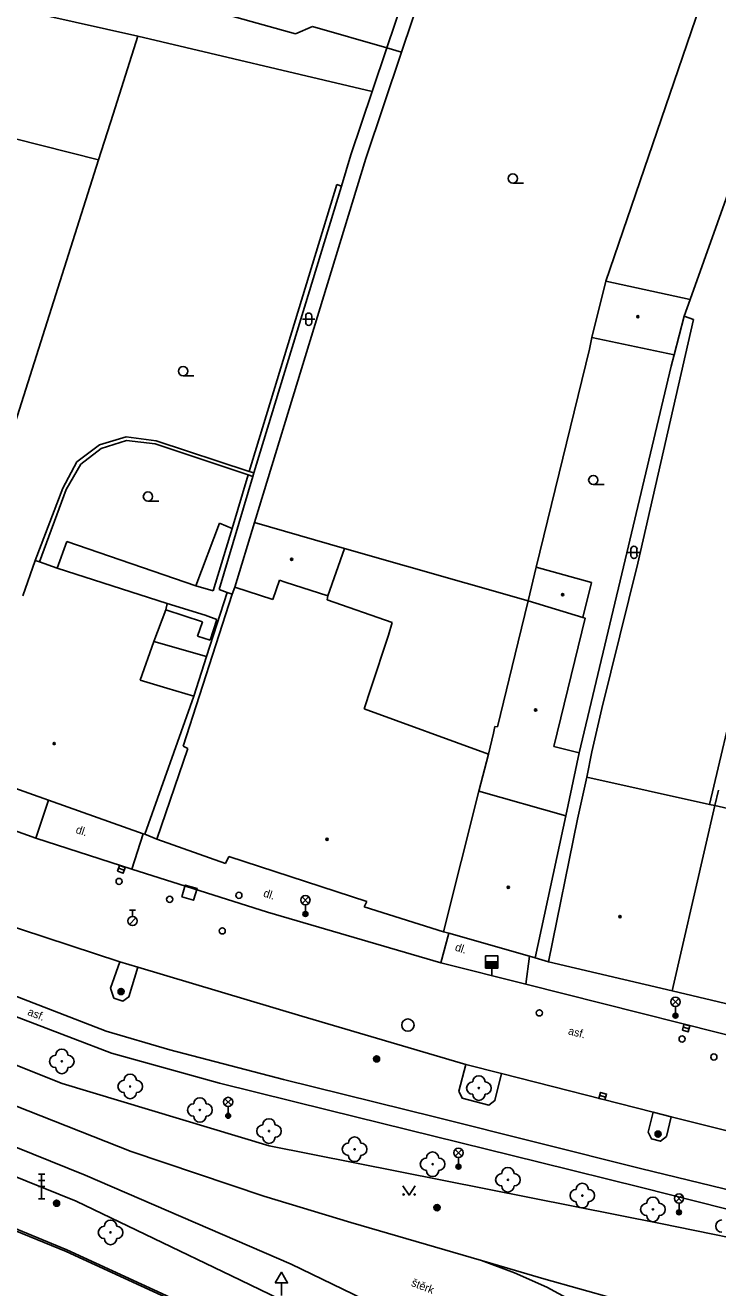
# Model space of a CAD drawing. Extents: x -600309 to -598967, y -1161267 to -1160292.
# Drawn here: x -600017 to -599960.7, y -1161167.5 to -1161065 of the extents above; entities that cross this region are included whole.
import ezdxf

# ---------------------------------------------------------------- set-up
doc = ezdxf.new("R2010")
doc.units = 0
for name, color, linetype in [('Level 10', 7, 'Continuous'), ('Level 11', 7, 'Continuous'), ('Level 13', 7, 'Continuous'), ('Level 14', 7, 'Continuous'), ('Level 22', 7, 'Continuous'), ('Level 25', 7, 'Continuous'), ('Level 26', 7, 'Continuous'), ('Level 27', 7, 'Continuous'), ('Level 28', 7, 'Continuous'), ('Level 33', 7, 'Continuous'), ('Level 34', 7, 'Continuous'), ('Level 36', 7, 'Continuous'), ('Level 39', 7, 'Continuous'), ('Level 40', 7, 'Continuous'), ('Level 5', 7, 'Continuous'), ('Level 51', 7, 'Continuous'), ('Level 52', 7, 'Continuous'), ('Level 54', 7, 'Continuous'), ('Level 7', 7, 'Continuous'), ('Level 9', 7, 'Continuous')]:
    doc.layers.add(name, color=color, linetype=linetype)

msp = doc.modelspace()

# ---------------------------------------------------------------- linework, layer by layer
at = {"layer": 'Level 10'}
for points in [[(-600016.1599, -1161131.01), (-600028.7199, -1161126.53)], [(-600008.36, -1161133.53), (-600016.1599, -1161131.01)], [(-599983.26, -1161141.1599), (-599997.33, -1161137.03), (-600008.36, -1161133.53)], [(-600028.39, -1161134.63), (-600023.46, -1161136.43), (-600009.34, -1161141.08)], [(-600009.34, -1161141.08), (-600007.88, -1161141.51)], [(-600007.88, -1161141.51), (-599994.56, -1161145.4699), (-599981.23, -1161149.4)], [(-599976.34, -1161142.88), (-599983.26, -1161141.1599)], [(-599932.42, -1161153.96), (-599936.27, -1161153.08), (-599952.82, -1161148.99), (-599954.4099, -1161148.4099), (-599976.34, -1161142.88)], [(-599981.23, -1161149.4), (-599978.33, -1161150.13)], [(-599978.33, -1161150.13), (-599966, -1161153.27)], [(-599966, -1161153.27), (-599964.52, -1161153.65)], [(-599964.52, -1161153.65), (-599939.5, -1161159.9099)]]:
    msp.add_lwpolyline(points, dxfattribs=at)
at = {"layer": 'Level 11'}
for points in [[(-599992.38, -1161153.1), (-600001.23, -1161150.93), (-600010.01, -1161148.49), (-600025.63, -1161142.54), (-600047.8, -1161133.93), (-600066.9099, -1161126.25), (-600071.24, -1161124.36), (-600084.2199, -1161118.67), (-600093.96, -1161114.55), (-600106.27, -1161109.6599), (-600141.52, -1161095.62), (-600170.63, -1161084.1), (-600197.34, -1161074.45), (-600220.27, -1161066.13)], [(-600029.52, -1161071.27), (-600011.07, -1161075.93)], [(-600016.1599, -1161131.01), (-600015.13, -1161127.94)], [(-600008.36, -1161133.53), (-600007.46, -1161130.6599)], [(-600006.35, -1161131.1), (-600007.32, -1161130.71)], [(-600010.46, -1161146.71), (-600038.83, -1161135.74)], [(-599983.26, -1161141.1599), (-599982.59, -1161138.75)], [(-599976.34, -1161142.88), (-599976.05, -1161140.61)], [(-599974.49, -1161141.08), (-599975.57, -1161140.75)], [(-600007.88, -1161141.51), (-600008.62, -1161143.92), (-600009.11, -1161144.26), (-600009.83, -1161144.01), (-600010.1, -1161143.2), (-600009.34, -1161141.08)], [(-600010.46, -1161146.71), (-600005.28, -1161148.21), (-599996.03, -1161150.62), (-599983.6599, -1161153.67)], [(-599978.33, -1161150.13), (-599978.86, -1161152.33), (-599979.35, -1161152.7), (-599981.53, -1161152.15), (-599981.79, -1161151.58), (-599981.23, -1161149.4)], [(-599992.38, -1161153.1), (-599975.26, -1161157.34), (-599966.94, -1161159.4), (-599946.69, -1161164.52), (-599944.2199, -1161165.09)], [(-599964.52, -1161153.65), (-599964.92, -1161155.25), (-599965.4, -1161155.64), (-599966.13, -1161155.44), (-599966.39, -1161154.89), (-599966, -1161153.27)], [(-599967.01, -1161157.86), (-599983.6599, -1161153.67)], [(-599863.64, -1161184.68), (-599889.92, -1161177.65), (-599907.2809, -1161172.7877), (-599916.52, -1161170.2), (-599932.76, -1161165.82), (-599934.95, -1161165.24), (-599946.09, -1161162.38), (-599957.33, -1161160.21), (-599967.01, -1161157.86)]]:
    msp.add_lwpolyline(points, dxfattribs=at)
at = {"layer": 'Level 13'}
for points in [[(-600008.43, -1161156.46), (-600028.28, -1161148.6599)], [(-600029.42, -1161151.45), (-600020.65, -1161154.98), (-600012.1599, -1161158.38)], [(-600008.43, -1161156.46), (-599997.65, -1161160.09), (-599990.56, -1161162.23), (-599979.95, -1161165.32)], [(-600012.1599, -1161158.38), (-599995.42, -1161165.61)], [(-599979.95, -1161165.32), (-599977.26, -1161166.33), (-599974.63, -1161167.5), (-599972.08, -1161168.86), (-599969.64, -1161170.37)], [(-599979.95, -1161165.32), (-599974.87, -1161166.8), (-599969.08, -1161168.43), (-599962.98, -1161170.1599), (-599954.07, -1161172.69)], [(-599995.42, -1161165.61), (-599987.87, -1161169.28), (-599986.57, -1161169.9099)]]:
    msp.add_lwpolyline(points, dxfattribs=at)
at = {"layer": 'Level 14'}
msp.add_lwpolyline([(-600209.68, -1161081.29), (-600207.11, -1161082.21), (-600207.29, -1161083.09), (-600203.81, -1161084.18), (-600189.29, -1161089.35), (-600180.35, -1161092.69), (-600160.29, -1161100.77), (-600144.28, -1161107.3), (-600111.05, -1161120.77), (-600060.34, -1161141.37), (-600012.89, -1161160.49), (-600000.2641, -1161166.5758), (-599990.94, -1161171.07)], dxfattribs=at)
at = {"layer": 'Level 22'}
for centre in [(-600014.06, -1161149.15), (-600008.5, -1161151.19), (-599980.1599, -1161151.32), (-600002.84, -1161153.1), (-599997.2199, -1161154.81), (-599990.26, -1161156.29), (-599983.92, -1161157.5), (-599977.8, -1161158.77), (-599971.75, -1161160.05), (-599966.01, -1161161.17), (-600010.1, -1161163.04)]:
    msp.add_circle(centre, 0.05, dxfattribs=at)
for centre, start, end in [((-600014.56, -1161149.15), 90, 270), ((-600014.06, -1161148.65), 0, 180), ((-600013.56, -1161149.15), 270, 90), ((-600014.06, -1161149.65), 180, 0), ((-600008.5, -1161150.69), 0, 180), ((-600009, -1161151.19), 90, 270), ((-600008, -1161151.19), 270, 90), ((-599980.6599, -1161151.32), 90, 270), ((-599980.1599, -1161150.82), 0, 180), ((-599979.6599, -1161151.32), 270, 90), ((-600008.5, -1161151.69), 180, 0), ((-600002.84, -1161152.6), 0, 180), ((-599980.1599, -1161151.82), 180, 0), ((-600003.34, -1161153.1), 90, 270), ((-600002.34, -1161153.1), 270, 90), ((-600002.84, -1161153.6), 180, 0), ((-599997.2199, -1161154.31), 0, 180), ((-599997.7199, -1161154.81), 90, 270), ((-599997.2199, -1161155.31), 180, 0), ((-599996.7199, -1161154.81), 270, 90), ((-599990.26, -1161155.79), 0, 180), ((-599990.76, -1161156.29), 90, 270), ((-599989.76, -1161156.29), 270, 90), ((-599990.26, -1161156.79), 180, 0), ((-599984.42, -1161157.5), 90, 270), ((-599983.92, -1161157), 0, 180), ((-599983.42, -1161157.5), 270, 90), ((-599983.92, -1161158), 180, 0), ((-599978.3, -1161158.77), 90, 270), ((-599977.8, -1161158.27), 0, 180), ((-599977.3, -1161158.77), 270, 90), ((-599977.8, -1161159.27), 180, 0), ((-599971.75, -1161159.55), 0, 180), ((-599972.25, -1161160.05), 90, 270), ((-599971.25, -1161160.05), 270, 90), ((-599966.01, -1161160.67), 0, 180), ((-599971.75, -1161160.55), 180, 0), ((-599966.51, -1161161.17), 90, 270), ((-599965.51, -1161161.17), 270, 90), ((-600010.1, -1161162.54), 0, 180), ((-599966.01, -1161161.67), 180, 0), ((-599960.4099, -1161162.53), 90, 270), ((-600010.6, -1161163.04), 90, 270), ((-600009.6, -1161163.04), 270, 90), ((-600010.1, -1161163.54), 180, 0)]:
    msp.add_arc(centre, 0.5, start, end, dxfattribs=at)
at = {"layer": 'Level 25'}
for centre, radius in [((-600009.24, -1161143.48), 0.25), ((-600009.24, -1161143.48), 0.2), ((-600009.24, -1161143.48), 0.15), ((-600009.24, -1161143.48), 0.1), ((-600009.24, -1161143.48), 0.05), ((-599988.48, -1161148.95), 0.25), ((-599988.48, -1161148.95), 0.2), ((-599988.48, -1161148.95), 0.15), ((-599988.48, -1161148.95), 0.1), ((-599988.48, -1161148.95), 0.05), ((-599965.59, -1161155.06), 0.25), ((-599965.59, -1161155.06), 0.2), ((-599965.59, -1161155.06), 0.15), ((-599965.59, -1161155.06), 0.1), ((-599965.59, -1161155.06), 0.05), ((-600014.49, -1161160.67), 0.25), ((-600014.49, -1161160.67), 0.2), ((-600014.49, -1161160.67), 0.15), ((-600014.49, -1161160.67), 0.1), ((-600014.49, -1161160.67), 0.05), ((-599983.56, -1161161.03), 0.25), ((-599983.56, -1161161.03), 0.2), ((-599983.56, -1161161.03), 0.15), ((-599983.56, -1161161.03), 0.1), ((-599983.56, -1161161.03), 0.05)]:
    msp.add_circle(centre, radius, dxfattribs=at)
at = {"layer": 'Level 26'}
msp.add_lwpolyline([(-600004.3095, -1161135.791), (-600003.349, -1161136.0695), (-600003.0705, -1161135.109), (-600004.031, -1161134.8305)], close=True, dxfattribs=at)
at = {"layer": 'Level 27'}
for p, q in [((-600009.4664, -1161133.4686), (-600008.9936, -1161133.6314)), ((-599963.5514, -1161146.3851), (-599963.0686, -1161146.5149)), ((-599970.3314, -1161151.9151), (-599969.8486, -1161152.0449))]:
    msp.add_line(p, q, dxfattribs=at)
for points in [[(-600009.5477, -1161133.705), (-600009.075, -1161133.8677), (-600008.9123, -1161133.395), (-600009.385, -1161133.2323)], [(-599963.6163, -1161146.6266), (-599963.1334, -1161146.7563), (-599963.0037, -1161146.2734), (-599963.4866, -1161146.1437)], [(-599970.3963, -1161152.1566), (-599969.9134, -1161152.2863), (-599969.7837, -1161151.8034), (-599970.2666, -1161151.6737)]]:
    msp.add_lwpolyline(points, close=True, dxfattribs=at)
msp.add_circle((-599985.93, -1161146.2), 0.5, dxfattribs=at)
at = {"layer": 'Level 28'}
for p, q in [((-600008.568, -1161138.022), (-600008.038, -1161137.492)), ((-600008.56, -1161136.875), (-600008.06, -1161136.875)), ((-600008.31, -1161137.375), (-600008.31, -1161136.875)), ((-599979.61, -1161141.08), (-599978.61, -1161141.08)), ((-599979.61, -1161141.13), (-599978.61, -1161141.13)), ((-599979.61, -1161141.18), (-599978.61, -1161141.18)), ((-599979.61, -1161141.23), (-599978.61, -1161141.23)), ((-599979.61, -1161141.28), (-599978.61, -1161141.28)), ((-599979.61, -1161141.33), (-599978.61, -1161141.33)), ((-599979.61, -1161141.38), (-599978.61, -1161141.38)), ((-599979.61, -1161141.43), (-599978.61, -1161141.43)), ((-599979.61, -1161141.48), (-599978.61, -1161141.48)), ((-599979.61, -1161141.53), (-599978.61, -1161141.53)), ((-599979.11, -1161141.58), (-599979.11, -1161142.11))]:
    msp.add_line(p, q, dxfattribs=at)
msp.add_lwpolyline([(-599979.61, -1161141.58), (-599978.61, -1161141.58), (-599978.61, -1161140.58), (-599979.61, -1161140.58)], close=True, dxfattribs=at)
for centre, radius in [((-600009.4, -1161134.54), 0.25), ((-600005.29, -1161135.99), 0.25), ((-599999.67, -1161135.67), 0.25), ((-600008.31, -1161137.75), 0.375), ((-600001.02, -1161138.55), 0.25), ((-599975.24, -1161145.21), 0.25), ((-599963.64, -1161147.33), 0.25), ((-599961.06, -1161148.8), 0.25)]:
    msp.add_circle(centre, radius, dxfattribs=at)
at = {"layer": 'Level 33'}
for p, q in [((-599994.525, -1161136.32), (-599993.995, -1161135.79)), ((-599994.525, -1161135.79), (-599993.995, -1161136.32)), ((-599994.26, -1161136.43), (-599994.26, -1161137.18)), ((-599964.445, -1161144.58), (-599963.915, -1161144.05)), ((-599964.445, -1161144.05), (-599963.915, -1161144.58)), ((-599964.18, -1161144.69), (-599964.18, -1161145.44)), ((-600000.805, -1161152.71), (-600000.275, -1161152.18)), ((-600000.805, -1161152.18), (-600000.275, -1161152.71)), ((-600000.54, -1161152.82), (-600000.54, -1161153.57)), ((-599982.085, -1161156.84), (-599981.555, -1161156.31)), ((-599982.085, -1161156.31), (-599981.555, -1161156.84)), ((-599981.82, -1161156.95), (-599981.82, -1161157.7)), ((-600015.95, -1161158.32), (-600015.45, -1161158.32)), ((-600015.7, -1161160.32), (-600015.7, -1161158.32)), ((-600015.95, -1161158.82), (-600015.45, -1161158.82)), ((-600015.95, -1161159.32), (-600015.45, -1161159.32)), ((-600015.95, -1161160.32), (-600015.45, -1161160.32)), ((-599964.155, -1161160.5499), (-599963.625, -1161160.0199)), ((-599964.155, -1161160.0199), (-599963.625, -1161160.5499)), ((-599963.89, -1161160.6599), (-599963.89, -1161161.4099))]:
    msp.add_line(p, q, dxfattribs=at)
for centre, radius in [((-599994.26, -1161136.055), 0.375), ((-599994.26, -1161137.18), 0.2), ((-599994.26, -1161137.18), 0.1445), ((-599994.26, -1161137.18), 0.0876), ((-599964.18, -1161144.315), 0.375), ((-599964.18, -1161145.44), 0.2), ((-599964.18, -1161145.44), 0.1445), ((-599964.18, -1161145.44), 0.0876), ((-600000.54, -1161152.445), 0.375), ((-600000.54, -1161153.57), 0.2), ((-600000.54, -1161153.57), 0.1445), ((-600000.54, -1161153.57), 0.0876), ((-599981.82, -1161156.575), 0.375), ((-599981.82, -1161157.7), 0.2), ((-599981.82, -1161157.7), 0.1445), ((-599981.82, -1161157.7), 0.0876), ((-599963.89, -1161160.2849), 0.375), ((-599963.89, -1161161.4099), 0.2), ((-599963.89, -1161161.4099), 0.1445), ((-599963.89, -1161161.4099), 0.0876)]:
    msp.add_circle(centre, radius, dxfattribs=at)
at = {"layer": 'Level 34'}
msp.add_line((-599996.21, -1161167.1419), (-599996.21, -1161168.1599), dxfattribs=at)
msp.add_lwpolyline([(-599996.71, -1161167.1419), (-599995.71, -1161167.1419), (-599996.21, -1161166.2759)], close=True, dxfattribs=at)
at = {"layer": 'Level 36'}
for p, q in [((-599977.4, -1161077.825), (-599976.525, -1161077.825)), ((-599994.236, -1161088.626), (-599994.236, -1161089.126)), ((-599993.736, -1161088.626), (-599993.736, -1161089.126)), ((-599994.486, -1161088.876), (-599993.486, -1161088.876)), ((-600004.2, -1161093.475), (-600003.325, -1161093.475)), ((-599970.86, -1161102.315), (-599969.985, -1161102.315)), ((-600007.06, -1161103.655), (-600006.185, -1161103.655)), ((-599968.056, -1161107.816), (-599967.056, -1161107.816)), ((-599967.806, -1161107.566), (-599967.806, -1161108.066)), ((-599967.306, -1161107.566), (-599967.306, -1161108.066))]:
    msp.add_line(p, q, dxfattribs=at)
msp.add_lwpolyline([(-599986.33, -1161159.26), (-599985.83, -1161160.01), (-599985.33, -1161159.26)], dxfattribs=at)
for centre, radius in [((-599977.4001, -1161077.4499), 0.375), ((-600004.2001, -1161093.0999), 0.375), ((-599970.8601, -1161101.9399), 0.375), ((-600007.0601, -1161103.2799), 0.375), ((-599986.2802, -1161159.9598), 0.05), ((-599985.3808, -1161159.9598), 0.05)]:
    msp.add_circle(centre, radius, dxfattribs=at)
for centre, start, end in [((-599993.9857, -1161088.6263), 0, 180), ((-599993.9857, -1161089.1263), 180, 0), ((-599967.5557, -1161107.5663), 0, 180), ((-599967.5557, -1161108.0663), 180, 0)]:
    msp.add_arc(centre, 0.25, start, end, dxfattribs=at)
at = {"layer": 'Level 39'}
for centre, radius in [((-599967.24, -1161088.67), 0.09), ((-599967.24, -1161088.67), 0.0398), ((-599995.38, -1161108.38), 0.09), ((-599995.38, -1161108.38), 0.0398), ((-599973.35, -1161111.25), 0.09), ((-599973.35, -1161111.25), 0.0398), ((-599975.55, -1161120.61), 0.09), ((-599975.55, -1161120.61), 0.0398), ((-600014.68, -1161123.34), 0.09), ((-600014.68, -1161123.34), 0.0398), ((-599992.5, -1161131.12), 0.09), ((-599992.5, -1161131.12), 0.0398), ((-599977.77, -1161135.01), 0.09), ((-599977.77, -1161135.01), 0.0398), ((-599968.69, -1161137.39), 0.09), ((-599968.69, -1161137.39), 0.0398)]:
    msp.add_circle(centre, radius, dxfattribs=at)
at = {"layer": 'Level 5'}
for points in [[(-600000.01, -1161110.63), (-599998.39, -1161105.39)], [(-599998.39, -1161105.39), (-599991.07, -1161107.51)], [(-599991.07, -1161107.51), (-599992.44, -1161111.35)], [(-600016.2199, -1161108.48), (-600017.23, -1161111.34)], [(-600016.2199, -1161108.48), (-600015.88, -1161108.58)], [(-600015.88, -1161108.58), (-600014.44, -1161109.09)], [(-600014.44, -1161109.09), (-600005.49, -1161111.9699)], [(-599976.1599, -1161111.75), (-599975.49, -1161109.01)], [(-599975.49, -1161109.01), (-599971, -1161110.27)], [(-599996.9099, -1161111.65), (-599996.36, -1161110.07)], [(-599996.36, -1161110.07), (-599995.9099, -1161110.24)], [(-600004.21, -1161123.56), (-600000.2, -1161111.2)], [(-600000.01, -1161110.63), (-600000.2, -1161111.2)], [(-600000.01, -1161110.63), (-599996.9099, -1161111.65)], [(-599995.9099, -1161110.24), (-599992.44, -1161111.35)], [(-599971, -1161110.27), (-599971.7, -1161113.1)], [(-600005.6, -1161112.49), (-600005.49, -1161111.9699)], [(-599992.44, -1161111.35), (-599992.5, -1161111.68)], [(-599992.5, -1161111.68), (-599987.2, -1161113.5)], [(-599976.96, -1161115.08), (-599976.1599, -1161111.75)], [(-599971.7, -1161113.1), (-599976.1599, -1161111.75)], [(-600006.59, -1161115.05), (-600005.6, -1161112.49)], [(-599971.52, -1161113.15), (-599974.06, -1161123.59)], [(-599971.7, -1161113.1), (-599971.52, -1161113.15)], [(-599987.2, -1161113.5), (-599987.5, -1161114.53)], [(-600007.7, -1161118.2), (-600006.59, -1161115.05)], [(-599987.5, -1161114.53), (-599988.95, -1161118.86)], [(-599978.65, -1161121.98), (-599976.96, -1161115.08)], [(-600005.52, -1161118.84), (-600007.7, -1161118.2)], [(-600003.34, -1161119.48), (-600005.52, -1161118.84)], [(-599988.95, -1161118.86), (-599989.49, -1161120.52)], [(-600003.34, -1161119.48), (-600007.32, -1161130.71)], [(-599989.49, -1161120.52), (-599979.39, -1161124.2)], [(-599979.39, -1161124.2), (-599978.98, -1161122.5)], [(-599978.98, -1161122.5), (-599978.85, -1161121.95)], [(-599978.85, -1161121.95), (-599978.65, -1161121.98)], [(-600015.13, -1161127.94), (-600026.28, -1161123.99)], [(-600006.35, -1161131.1), (-600003.82, -1161123.75)], [(-600003.82, -1161123.75), (-600004.21, -1161123.56)], [(-599979.39, -1161124.2), (-599980.15, -1161127.2)], [(-599974.06, -1161123.59), (-599972.01, -1161124.1)], [(-599973.1, -1161129.2), (-599972.01, -1161124.1)], [(-599971.39, -1161126.06), (-599972.15, -1161129.4699)], [(-599971.39, -1161126.06), (-599961.4, -1161128.29)], [(-599980.15, -1161127.2), (-599983.03, -1161138.63)], [(-599980.15, -1161127.2), (-599973.1, -1161129.2)], [(-600007.46, -1161130.6599), (-600015.13, -1161127.94)], [(-599960.98, -1161128.38), (-599961.76, -1161131.79)], [(-599961.4, -1161128.29), (-599960.98, -1161128.38)], [(-599960.98, -1161128.38), (-599956.19, -1161129.49)], [(-599973.1, -1161129.2), (-599975.57, -1161140.75)], [(-599974.49, -1161141.08), (-599972.15, -1161129.4699)], [(-600007.32, -1161130.71), (-600007.46, -1161130.6599)], [(-600000.75, -1161133.07), (-600006.35, -1161131.1)], [(-600000.48, -1161132.51), (-600000.75, -1161133.07)], [(-599989.27, -1161136.1599), (-600000.48, -1161132.51)], [(-599961.76, -1161131.79), (-599964.45, -1161143.4099)], [(-599989.48, -1161136.6), (-599989.27, -1161136.1599)], [(-599983.03, -1161138.63), (-599989.48, -1161136.6)], [(-599982.59, -1161138.75), (-599983.03, -1161138.63)], [(-599976.05, -1161140.61), (-599982.59, -1161138.75)], [(-599975.57, -1161140.75), (-599976.05, -1161140.61)], [(-599964.45, -1161143.4099), (-599974.49, -1161141.08)], [(-599953.7199, -1161145.96), (-599964.45, -1161143.4099)]]:
    msp.add_lwpolyline(points, dxfattribs=at)
at = {"layer": 'Level 51'}
for points in [[(-599970.18, -1161015.28), (-599982.42, -1161051.36), (-599987.63, -1161066.84)], [(-599969.84, -1161085.78), (-599957.36, -1161049.29)], [(-599986.44, -1161067.18), (-599981.21, -1161051.6599)], [(-600027.23, -1161061.55), (-600025.5, -1161061.94), (-600007.88, -1161065.9)], [(-600005.59, -1161062.74), (-599995.07, -1161065.69)], [(-600007.88, -1161065.9), (-600009.89, -1161072.23)], [(-600007.88, -1161065.9), (-599988.83, -1161070.39)], [(-599995.07, -1161065.69), (-599993.68, -1161065.11)], [(-599993.68, -1161065.11), (-599987.63, -1161066.84)], [(-599955.2, -1161065.48), (-599962.99, -1161087.27)], [(-599987.63, -1161066.84), (-599988.83, -1161070.39)], [(-599987.63, -1161066.84), (-599986.44, -1161067.18)], [(-599989.35, -1161075.82), (-599986.44, -1161067.18)], [(-599991.33, -1161078.06), (-599990.56, -1161075.52), (-599988.83, -1161070.39)], [(-600009.89, -1161072.23), (-600011.07, -1161075.93), (-600019.08, -1161101.15)], [(-599998.39, -1161105.39), (-599989.35, -1161075.82)], [(-599991.33, -1161078.06), (-599998.34, -1161101.01), (-599998.44, -1161101.36)], [(-599991.33, -1161078.06), (-599991.71, -1161077.94)], [(-599962.71, -1161088.89), (-599963.46, -1161088.64)], [(-599967.23, -1161108.7), (-599962.71, -1161088.89)], [(-599970.99, -1161090.37), (-599971.18, -1161091.31)], [(-599971.18, -1161091.31), (-599975.49, -1161109.01)], [(-599964.52, -1161092.68), (-599968.28, -1161108.43)], [(-599964.29, -1161091.77), (-599964.52, -1161092.68)], [(-600011, -1161099.09), (-600008.84, -1161098.42)], [(-600008.84, -1161098.42), (-600006.38, -1161098.75)], [(-600006.38, -1161098.75), (-599998.82, -1161101.24)], [(-600012.84, -1161100.45), (-600011, -1161099.09)], [(-600013.99, -1161102.6), (-600012.84, -1161100.45)], [(-599998.52, -1161101.64), (-600001.27, -1161110.84)], [(-599998.82, -1161101.24), (-599998.44, -1161101.36)], [(-599998.44, -1161101.36), (-599998.52, -1161101.64)], [(-600016.2199, -1161108.48), (-600013.99, -1161102.6)], [(-599991.07, -1161107.51), (-599976.1599, -1161111.75)], [(-599968.28, -1161108.43), (-599972.01, -1161124.1)], [(-599970.1599, -1161120.49), (-599967.23, -1161108.7)], [(-600000.62, -1161111.06), (-600002.31, -1161116.28)], [(-600001.27, -1161110.84), (-600000.62, -1161111.06)], [(-600000.2, -1161111.2), (-600000.62, -1161111.06)], [(-600002.31, -1161116.28), (-600003.34, -1161119.48)], [(-599970.98, -1161124), (-599970.1599, -1161120.49)], [(-599971.39, -1161126.06), (-599970.98, -1161124)], [(-599960.67, -1161127.13), (-599960.98, -1161128.38)]]:
    msp.add_lwpolyline(points, dxfattribs=at)
at = {"layer": 'Level 52'}
for points in [[(-599969.84, -1161085.78), (-599970.99, -1161090.37)], [(-599962.99, -1161087.27), (-599969.84, -1161085.78)], [(-599962.99, -1161087.27), (-599963.46, -1161088.64)], [(-599963.46, -1161088.64), (-599964.29, -1161091.77)], [(-599964.29, -1161091.77), (-599970.99, -1161090.37)]]:
    msp.add_lwpolyline(points, dxfattribs=at)
at = {"layer": 'Level 54'}
for points in [[(-599991.71, -1161077.94), (-599998.82, -1161101.24)], [(-600010.85, -1161099.38), (-600008.79, -1161098.74)], [(-600008.79, -1161098.74), (-600006.46, -1161098.99)], [(-600012.52, -1161100.65), (-600010.85, -1161099.38)], [(-600006.46, -1161098.99), (-599998.9, -1161101.51)], [(-600013.71, -1161102.71), (-600012.52, -1161100.65)], [(-599998.9, -1161101.51), (-600000.21, -1161105.88)], [(-599998.9, -1161101.51), (-599998.52, -1161101.64)], [(-600015.88, -1161108.58), (-600013.71, -1161102.71)], [(-600003.1599, -1161110.52), (-600001.24, -1161105.43)], [(-600000.21, -1161105.88), (-600001.75, -1161110.94)], [(-600001.24, -1161105.43), (-600000.21, -1161105.88)], [(-600014.44, -1161109.09), (-600013.65, -1161106.93)], [(-600013.65, -1161106.93), (-600003.1599, -1161110.52)], [(-600001.75, -1161110.94), (-600003.1599, -1161110.52)], [(-600005.49, -1161111.9699), (-600002.4099, -1161112.92)], [(-600002.63, -1161113.46), (-600005.6, -1161112.49)], [(-600002.4099, -1161112.92), (-600001.46, -1161113.27)], [(-600001.46, -1161113.27), (-600001.99, -1161114.94)], [(-600003.02, -1161114.61), (-600002.63, -1161113.46)], [(-600006.59, -1161115.05), (-600002.31, -1161116.28)], [(-600001.99, -1161114.94), (-600003.02, -1161114.61)], [(-599959.06, -1161118.34), (-599961.4, -1161128.29)]]:
    msp.add_lwpolyline(points, dxfattribs=at)
at = {"layer": 'Level 7'}
for points in [[(-600035.74, -1161155.54), (-600031.61, -1161157.21), (-600022.53, -1161160.98), (-600013.7199, -1161164.6), (-600005.29, -1161168.45), (-599997.9099, -1161172.12), (-599989.27, -1161176.36), (-599982.84, -1161179.63), (-599974.34, -1161183.8)], [(-599975.45, -1161183.09), (-599982.77, -1161179.5), (-599989.2, -1161176.23), (-599997.84, -1161171.99), (-600000.0001, -1161170.9172), (-600005.23, -1161168.32), (-600013.6599, -1161164.46), (-600022.4699, -1161160.84), (-600031.55, -1161157.07), (-600035.71, -1161155.39)]]:
    msp.add_lwpolyline(points, dxfattribs=at)
at = {"layer": 'Level 9'}
msp.add_lwpolyline([(-599945.84, -1161166.45), (-599955.55, -1161164.33), (-599965.39, -1161162.33), (-599997.2, -1161156.01), (-600014.03, -1161150.96), (-600042.87, -1161139.4699), (-600081.25, -1161124.03), (-600095.2, -1161118.31), (-600186.62, -1161081.68)], dxfattribs=at)

# ---------------------------------------------------------------- texts
at = {"layer": 'Level 40'}
for s, rotation, p in [('dl.', 342.12, (-600012.98, -1161130.59)), ('dl.', 342.12, (-599997.73, -1161135.75)), ('dl.', 342.12, (-599982.15, -1161140.14)), ('asf.', 338.37, (-600016.9, -1161145.36)), ('asf.', 345.96, (-599972.95, -1161146.95)), ('štěrk', 338.98, (-599985.71, -1161167.37))]:
    msp.add_text(s, height=0.65, rotation=rotation, dxfattribs=at).set_placement(p)

doc.saveas('drawing.dxf')
